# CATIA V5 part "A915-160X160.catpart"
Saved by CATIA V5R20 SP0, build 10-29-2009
Part number: A915-160X160
Source: Unknown
Property "A": "110.000"
Property "ARTICLENO": "A915-160X160"
Property "BOMINFO": "A915-160X160"
Property "CODE": "A915-160X160"
Property "CREATOR": "CADENAS GmbH"
Property "D": "13.500"
Property "D1": "20.000"
Property "FORM": "C"
Property "L": "160.000"
Property "L1": "25.000"
Property "L2": "110.000"
Property "LINA": "A915-160X160"
Property "NB": "A915-160X160"
Property "NBSYN": "$CODE."
Property "NN": "A915"
Property "NT": "VDI 3357 Wear Plates, steel"
Property "SCREW": "M12x25"
Property "SUPPLIER": "CF"
Property "T": "13.000"
Property "W": "160.000"
Bounding box of the stored display mesh (mm): x 0 to 20, y 0 to 160, z -80 to 80
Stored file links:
  C:\Users\borellobunino\Desktop\3D X SITO CF\A915\GSB_OILLESS_G22501160160\CATIAV5\A915-160X160.catpart
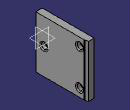
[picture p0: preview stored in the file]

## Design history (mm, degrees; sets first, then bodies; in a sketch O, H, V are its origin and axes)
Body1 "Geometry.1" (main body)
  Solid1 "A915-160X160.catpart": solid without history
